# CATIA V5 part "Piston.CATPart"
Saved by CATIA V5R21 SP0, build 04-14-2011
Part number: Piston
Bounding box of the stored display mesh (mm): x -46 to 46, y -45.932 to 45.932, z 0 to 70.683
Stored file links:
  D:\CATIA V5R21 E-RESOURCES\CATIA-V5R21\catia-v5r21-Prts\c13_catia_v5r21_prt\c13_catia_v5r21_figr_13-41\Part & Asm files\Piston.CATPart
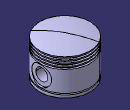
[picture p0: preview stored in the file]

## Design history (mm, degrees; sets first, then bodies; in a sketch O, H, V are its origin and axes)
Body1 (main body)
  Sketch1 on yz-plane, origin (0, 0, 0), H (0, 1, 0), V (0, 0, 1)
    line L1 (37, 0) -> (46, 0)
    line L2 (46, 0) -> (46, 5)
    construction line L3 (0, 62) -> (0, 0)
    point P2 (46, 65)
    line L4 (42.5, 45) -> (42.5, 48)
    point P5 (46, 48)
    point P6 (46, 50)
    point P7 (46, 53)
    point P8 (46, 55)
    point P9 (46, 58)
    point P10 (46, 60)
    line L5 (42.5, 48) -> (46, 48)
    line L6 (42.5, 45) -> (46, 45)
    line L7 (42.5, 50) -> (46, 50)
    point P13 (42.5, 50)
    line L8 (42.5, 53) -> (46, 53)
    point P14 (42.5, 53)
    line L9 (42.5, 55) -> (46, 55)
    point P15 (42.5, 55)
    line L10 (42.5, 58) -> (46, 58)
    point P16 (42.5, 58)
    line L11 (42.5, 60) -> (46, 60)
    point P17 (42.5, 60)
    line L12 (46, 48) -> (46, 50)
    line L13 (46, 53) -> (46, 55)
    line L14 (46, 58) -> (46, 60)
    line L15 (42.5, 50) -> (42.5, 53)
    line L16 (42.5, 55) -> (42.5, 58)
    line L17 (42.5, 60) -> (42.5, 63)
    line L18 (42.5, 63) -> (46, 63)
    point P18 (46, 63)
    line L19 (46, 63) -> (46, 65)
    line L20 (46, 5) -> (42.5, 5)
    point P20 (42.5, 5)
    line L21 (42.5, 5) -> (42.5, 7)
    line L22 (42.5, 7) -> (46, 7)
    point P22 (46, 7)
    line L23 (46, 7) -> (46, 45)
    point P23 (-46, 65)
    point P24 (-46, 63)
    construction line L24 (-46, 63) -> (-46, 65)
    arc A1 centre (0, -118.3167) radius 189 from (46, 65) to (0, 70.6833) ccw
    point P26 (0, 55)
    line L25 (37, 0) -> (37, 62)
    line L26 (37, 62) -> (0, 62)
    line L27 (0, 62) -> (0, 70.6833)
    construction arc A2 centre (0, -118.3167) radius 189 from (0, 70.6833) to (-46, 65) ccw
    distance L2 L4 = 3.5
    distance L6 L1 = 45
    length L4 = 3
    length L15 = 3
    length L16 = 3
    length L13 = 2
    length L12 = 2
    length L17 = 3
    length L19 = 2
    length L14 = 2
    length L21 = 2
    distance L1 L22 = 7
    radius A1 = 189
    length L26 = 37
    length L25 = 62
    distance L2 L3 = 46
    horizontal: L1 H, L5 H, L6 H, L7 H, L8 H, L9 H, L10 H, L11 H, L18 H, L20 H, L22 H, L26 H
    vertical: L2 V, L3 V, L12 V, L13 V, L14 V, L19 V, L21 V, L23 V, L25 V, L27 V, L17 V, L16 V, L15 V, L4 V
    coincidence: L2 P5, L2 P6, L2 P7, L2 P8, L2 P9, L2 P10, L4 P13, L4 P14, L4 P15, L4 P16, L4 P17, L2 L12, L12 L13, L13 L14, L4 L15, L15 L16, L16 L17, P18 L14, L14 L19, P20 L15, P22 L2, L2 L23, P26 L3, P26 L9, L1 H, A1 A2
    symmetry: P2 P23 L3, P18 P24 L3, L19 L24 L3
  Shaft1: profile Sketch1, axis Sketch1.V, angle 360
  Sketch2 on yz-plane, origin (0, 0, 0), H (0, 1, 0), V (0, 0, 1)
    circle A1 centre (0, 26) radius 19.5
    point P1 (0, 26)
    radius A1 = 19.5
    distance H P1 = 26
    coincidence: P1 V
  Pad1: profile Sketch2, direction (1, 0, 0), up to the existing solid (limit type 2), opposite side length -25
  Mirror1: of Pad1, Sketch2, about yz-plane
  Sketch3 on yz-plane, origin (0, 0, 0), H (0, 1, 0), V (0, 0, 1)
    circle A1 centre (0, 26) radius 18
    point P1 (0, 26)
    reference projected circle E1 centre (0, 26) radius 19.5 from edge of Pad1
    radius A1 = 18
    coincidence: P1 V
    concentricity: A1 E1
  Pocket1: profile Sketch3, direction (-1, 0, 0), length 42.5, opposite side length -50
  Mirror2: of Pocket1, Sketch3, about yz-plane
  Sketch4 on yz-plane, origin (0, 0, 0), H (0, 1, 0), V (0, 0, 1)
    circle A1 centre (0, 26) radius 11
    point P1 (0, 26)
    reference projected circle E1 centre (0, 26) radius 19.5 from edge of Pad1
    radius A1 = 11
    coincidence: P1 V
    concentricity: A1 E1
  Pocket2: profile Sketch4, direction (-1, 0, 0), length 50.5, mirrored extent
